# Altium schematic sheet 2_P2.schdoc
size 848 x 601 mm; Symbol: Sheet-Symbol_A0; Device: Sheet-Symbol_A0; Company: 嘉立创EDA; Version: V1.0; Page Size: A0; @Project Name: MX无人机3; @Page Count: 2; @Update Date: 2025-03-07; @Create Date: 2025-02-27; @Schematic Name: Schematic4; @Page No: 2; @Page Name: P2; @Board Name: 遥控; @Create Time: 13:19:18; @Update Time: 19:04:30; Width: 3304; Height: 2338; Region Start: 1; X Region Count: 6; Y Region Count: 4; Blade Width: 10; Title Block Position: 3
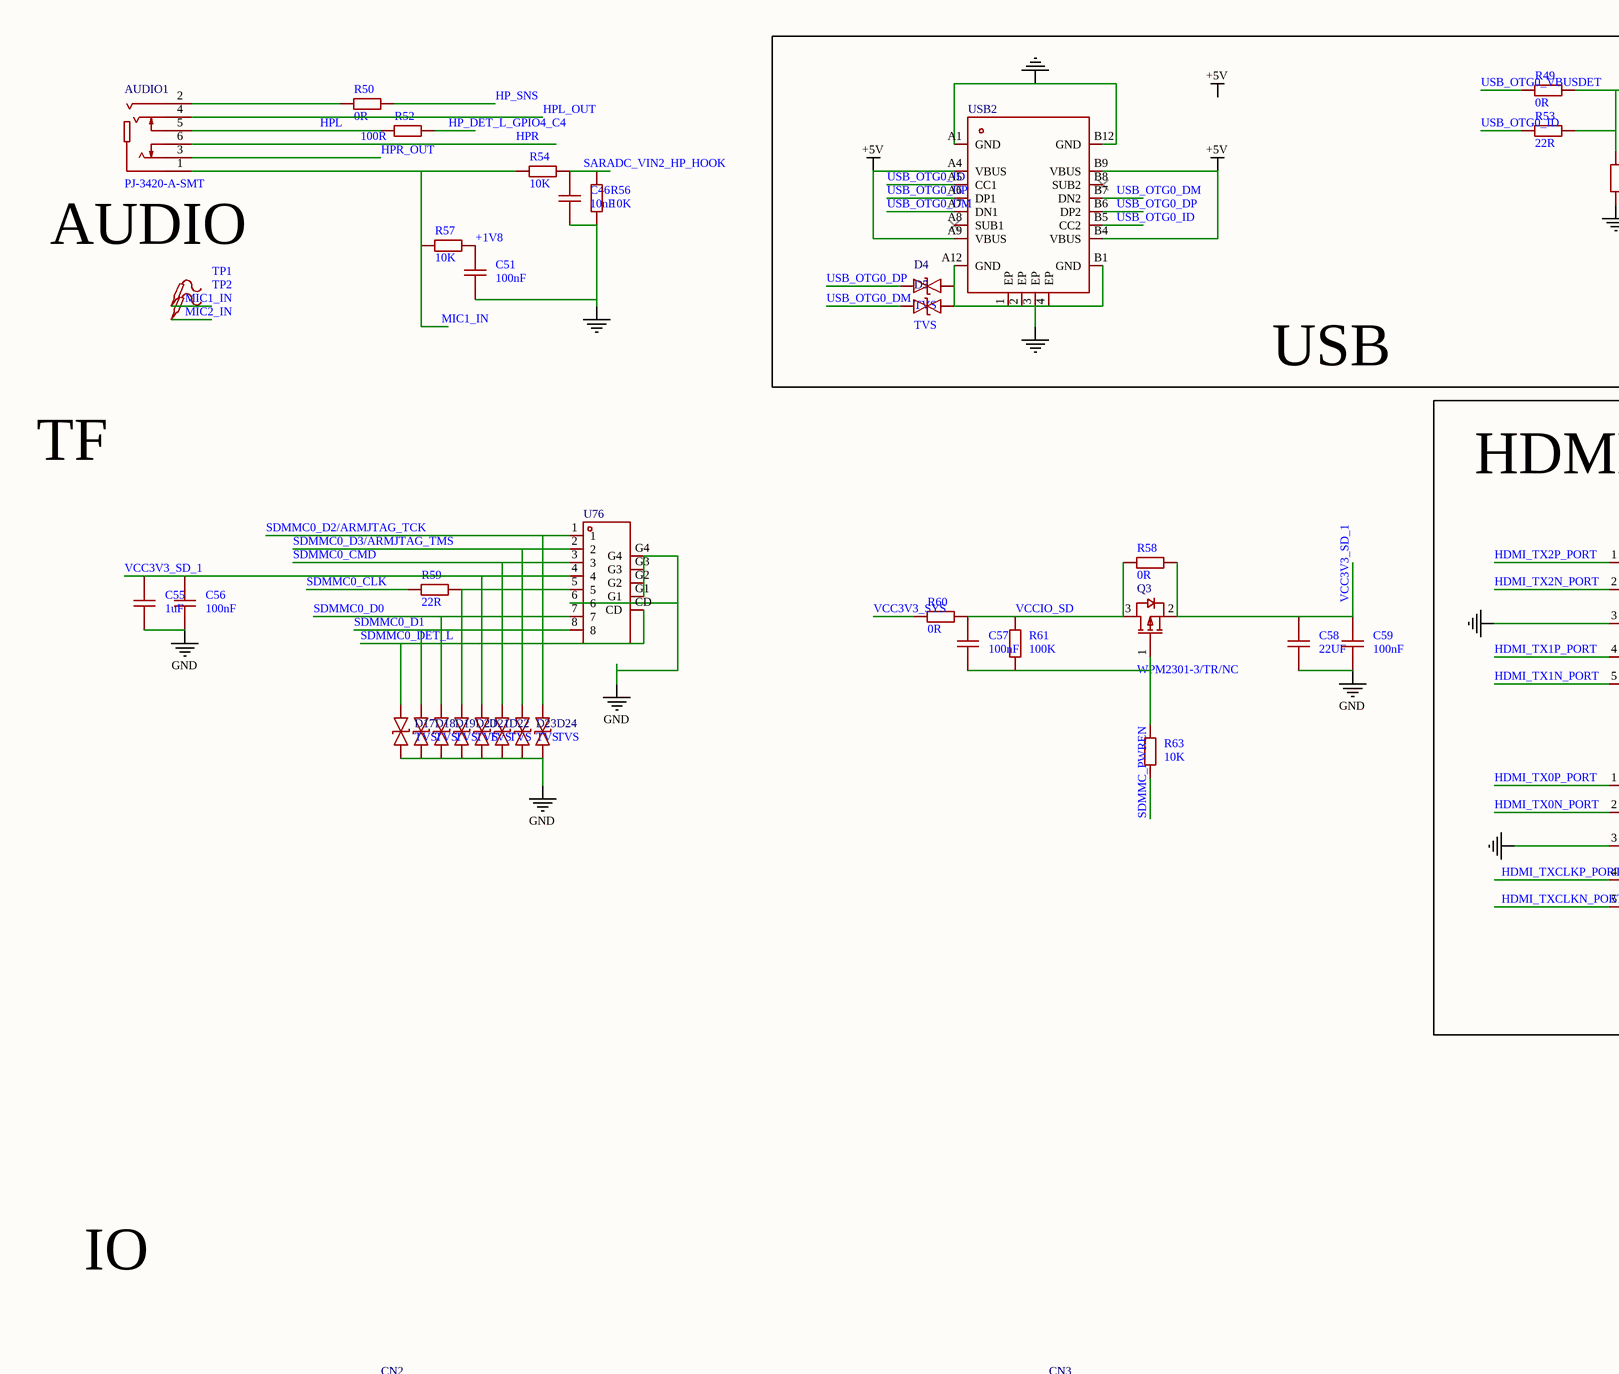
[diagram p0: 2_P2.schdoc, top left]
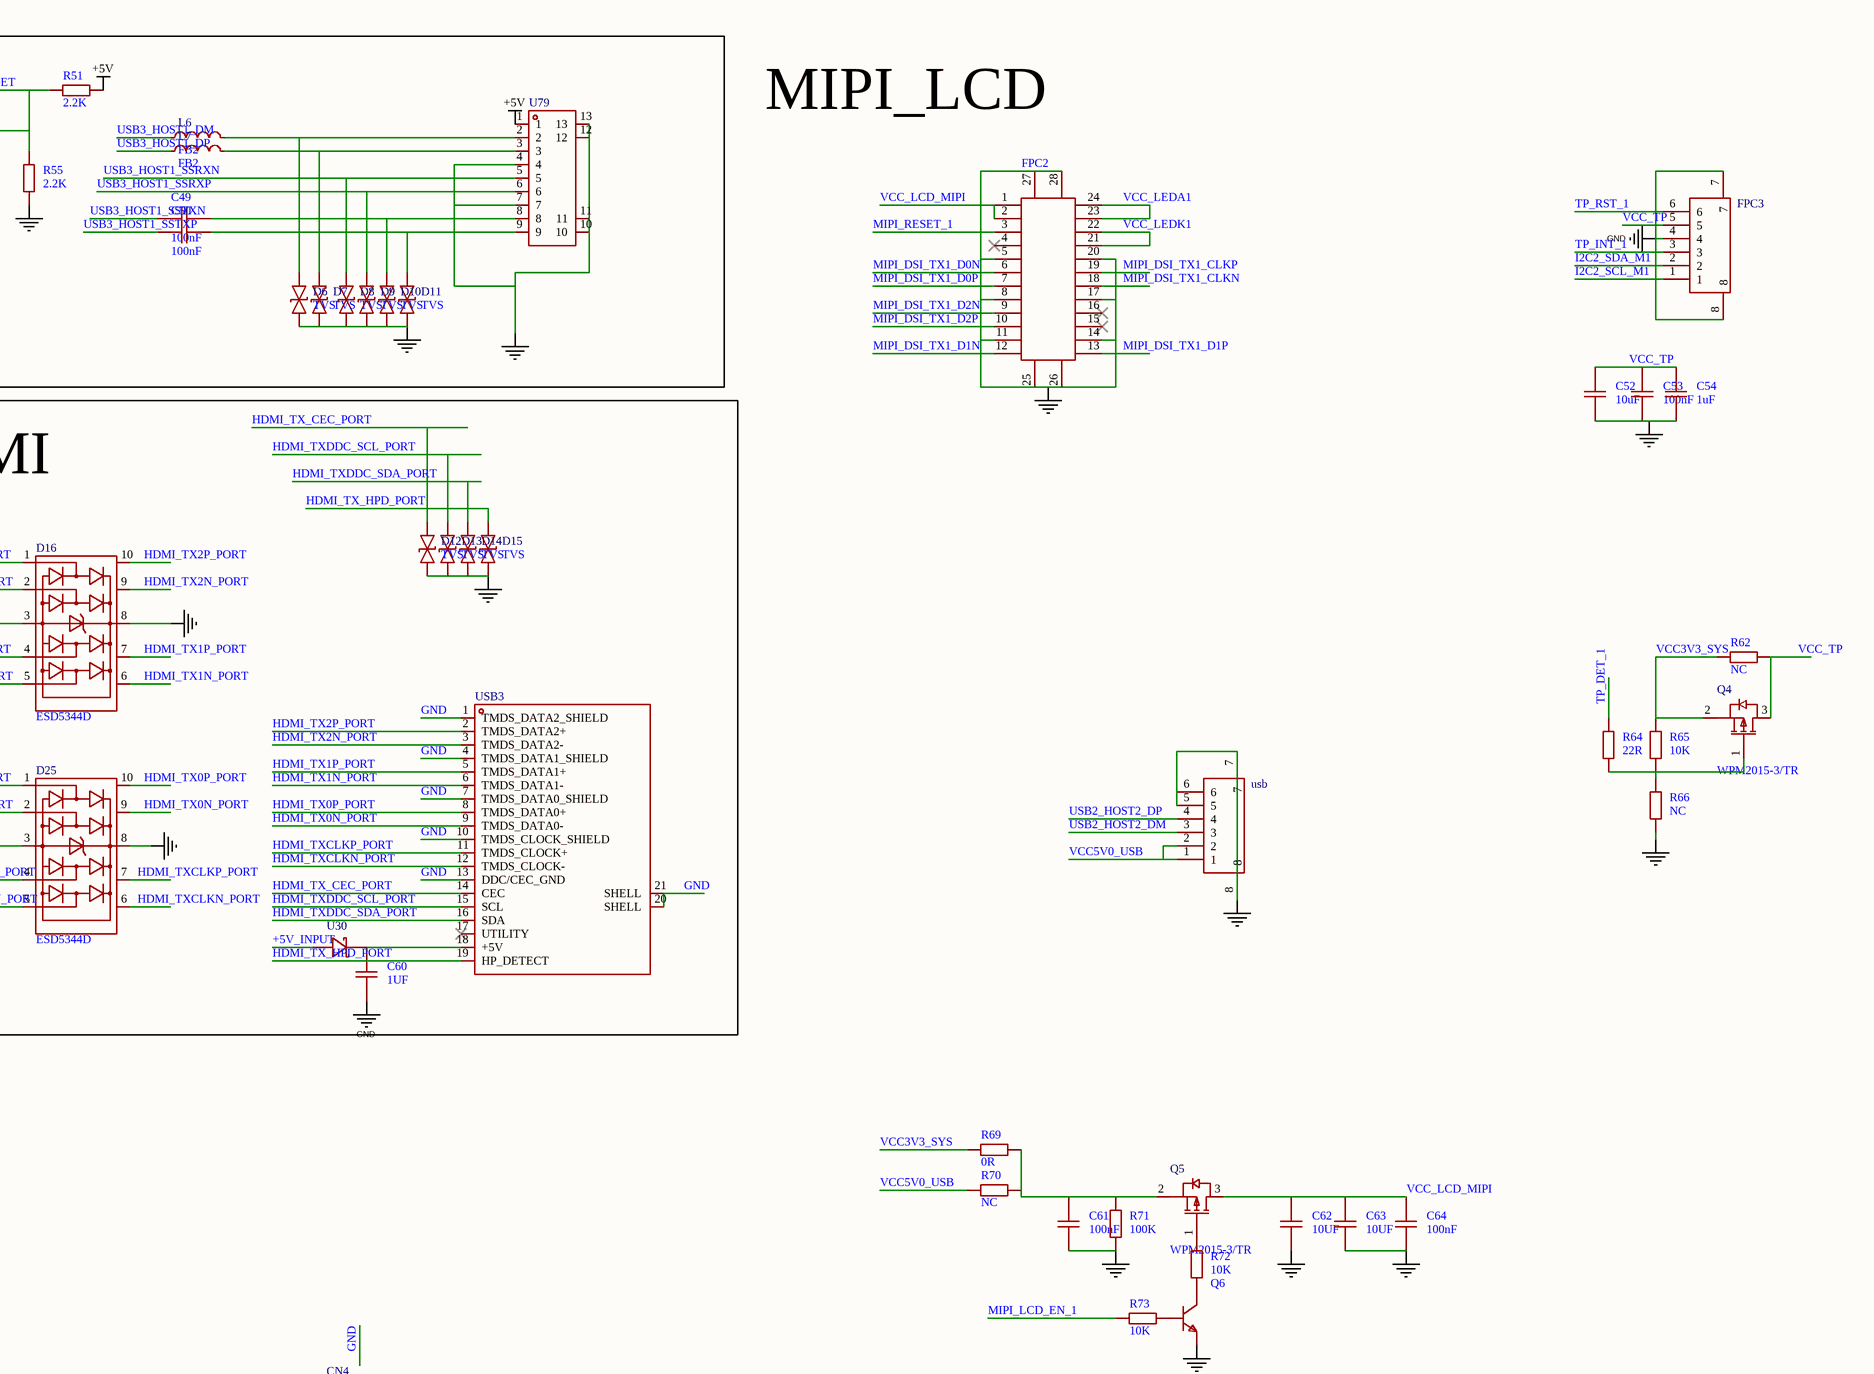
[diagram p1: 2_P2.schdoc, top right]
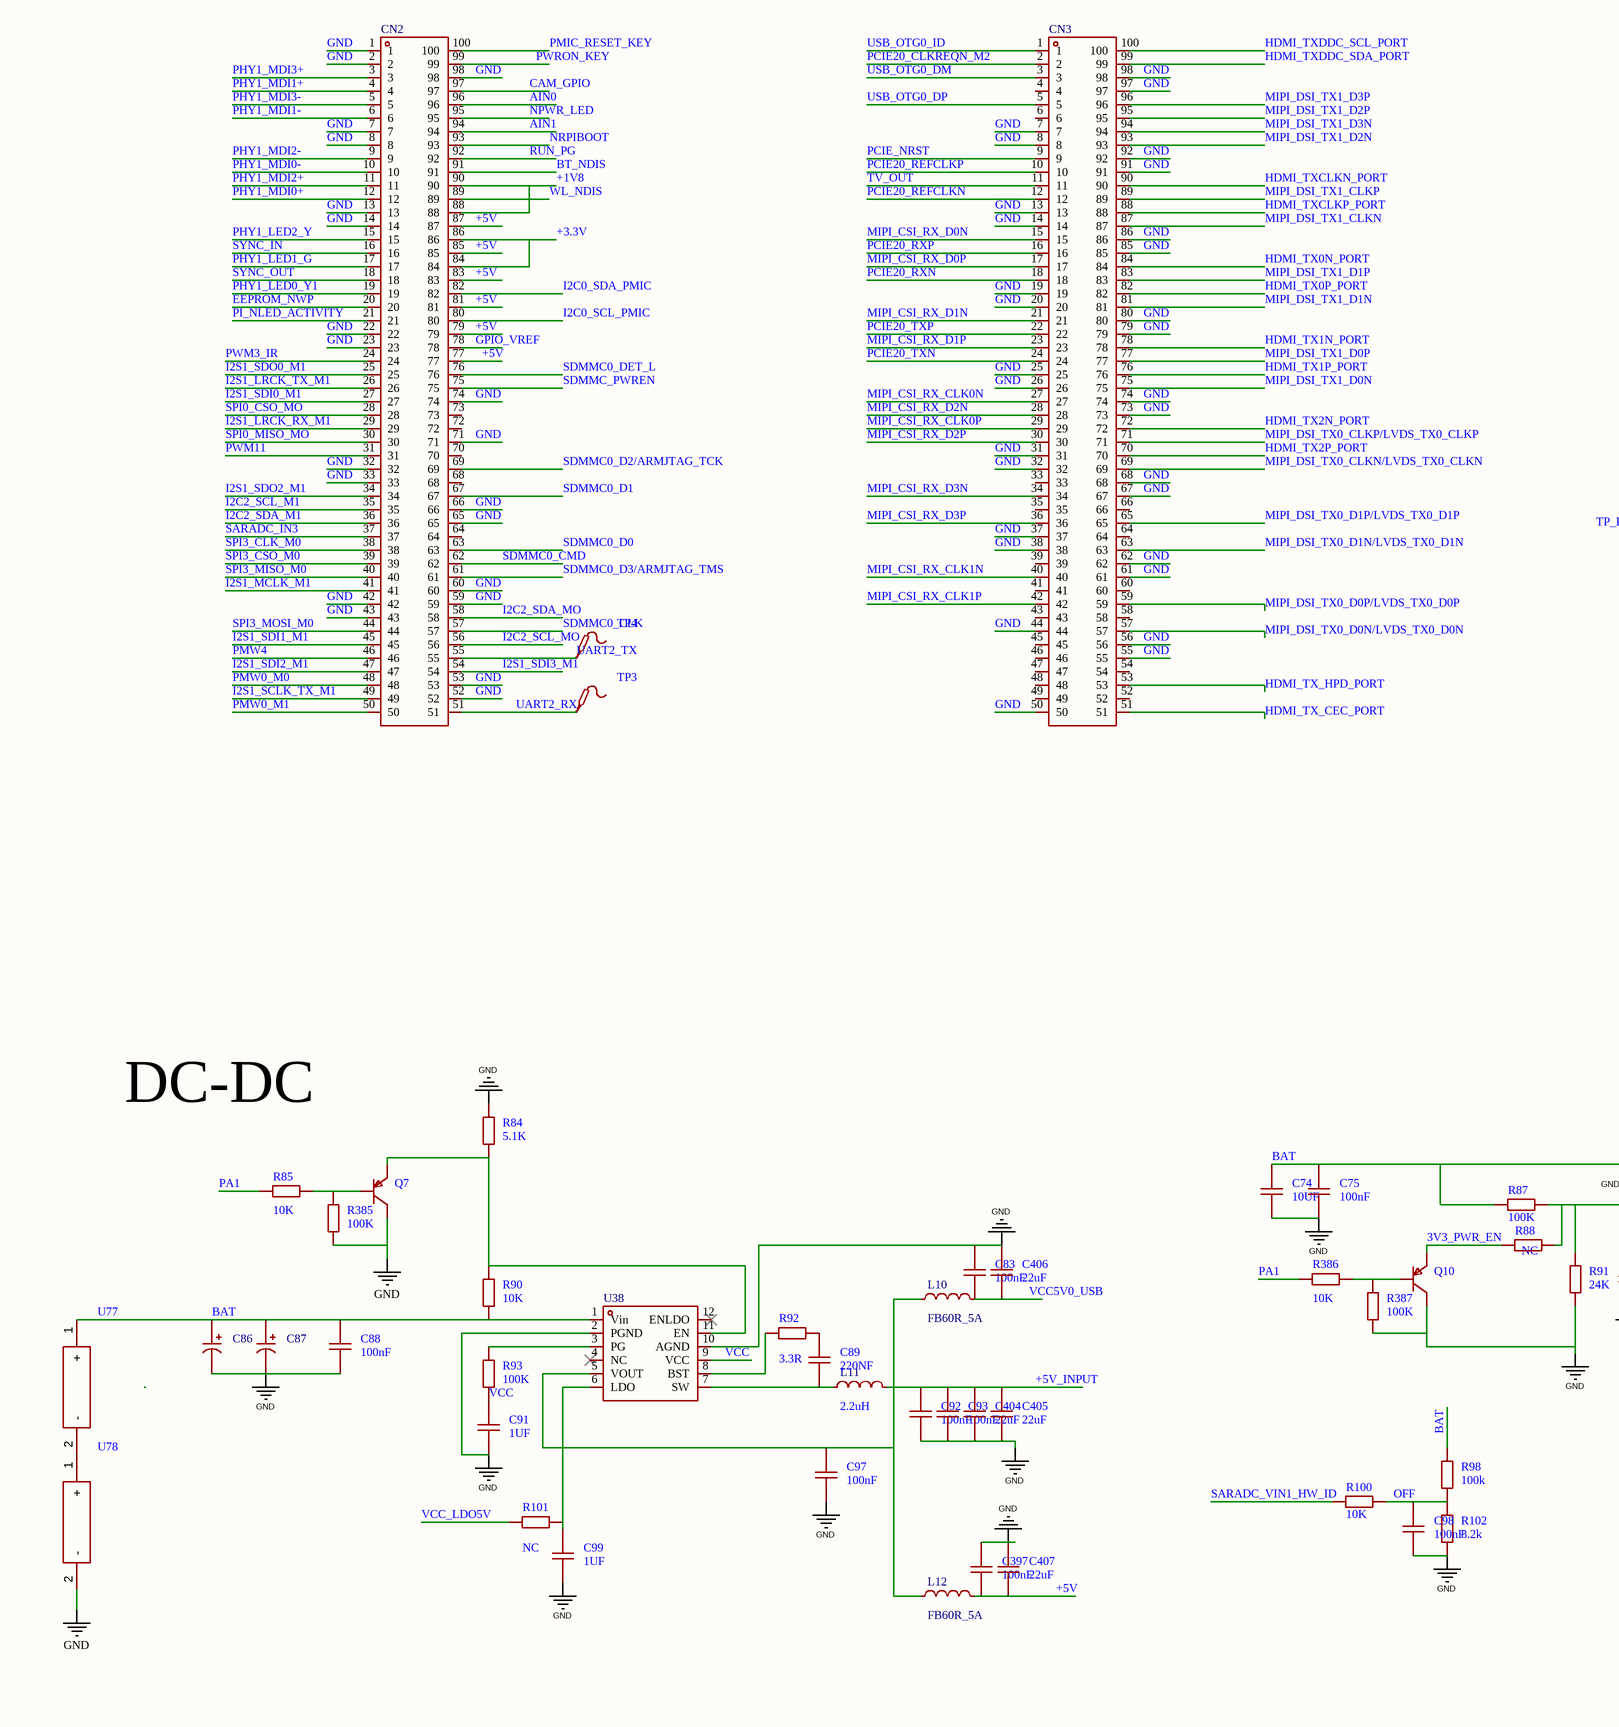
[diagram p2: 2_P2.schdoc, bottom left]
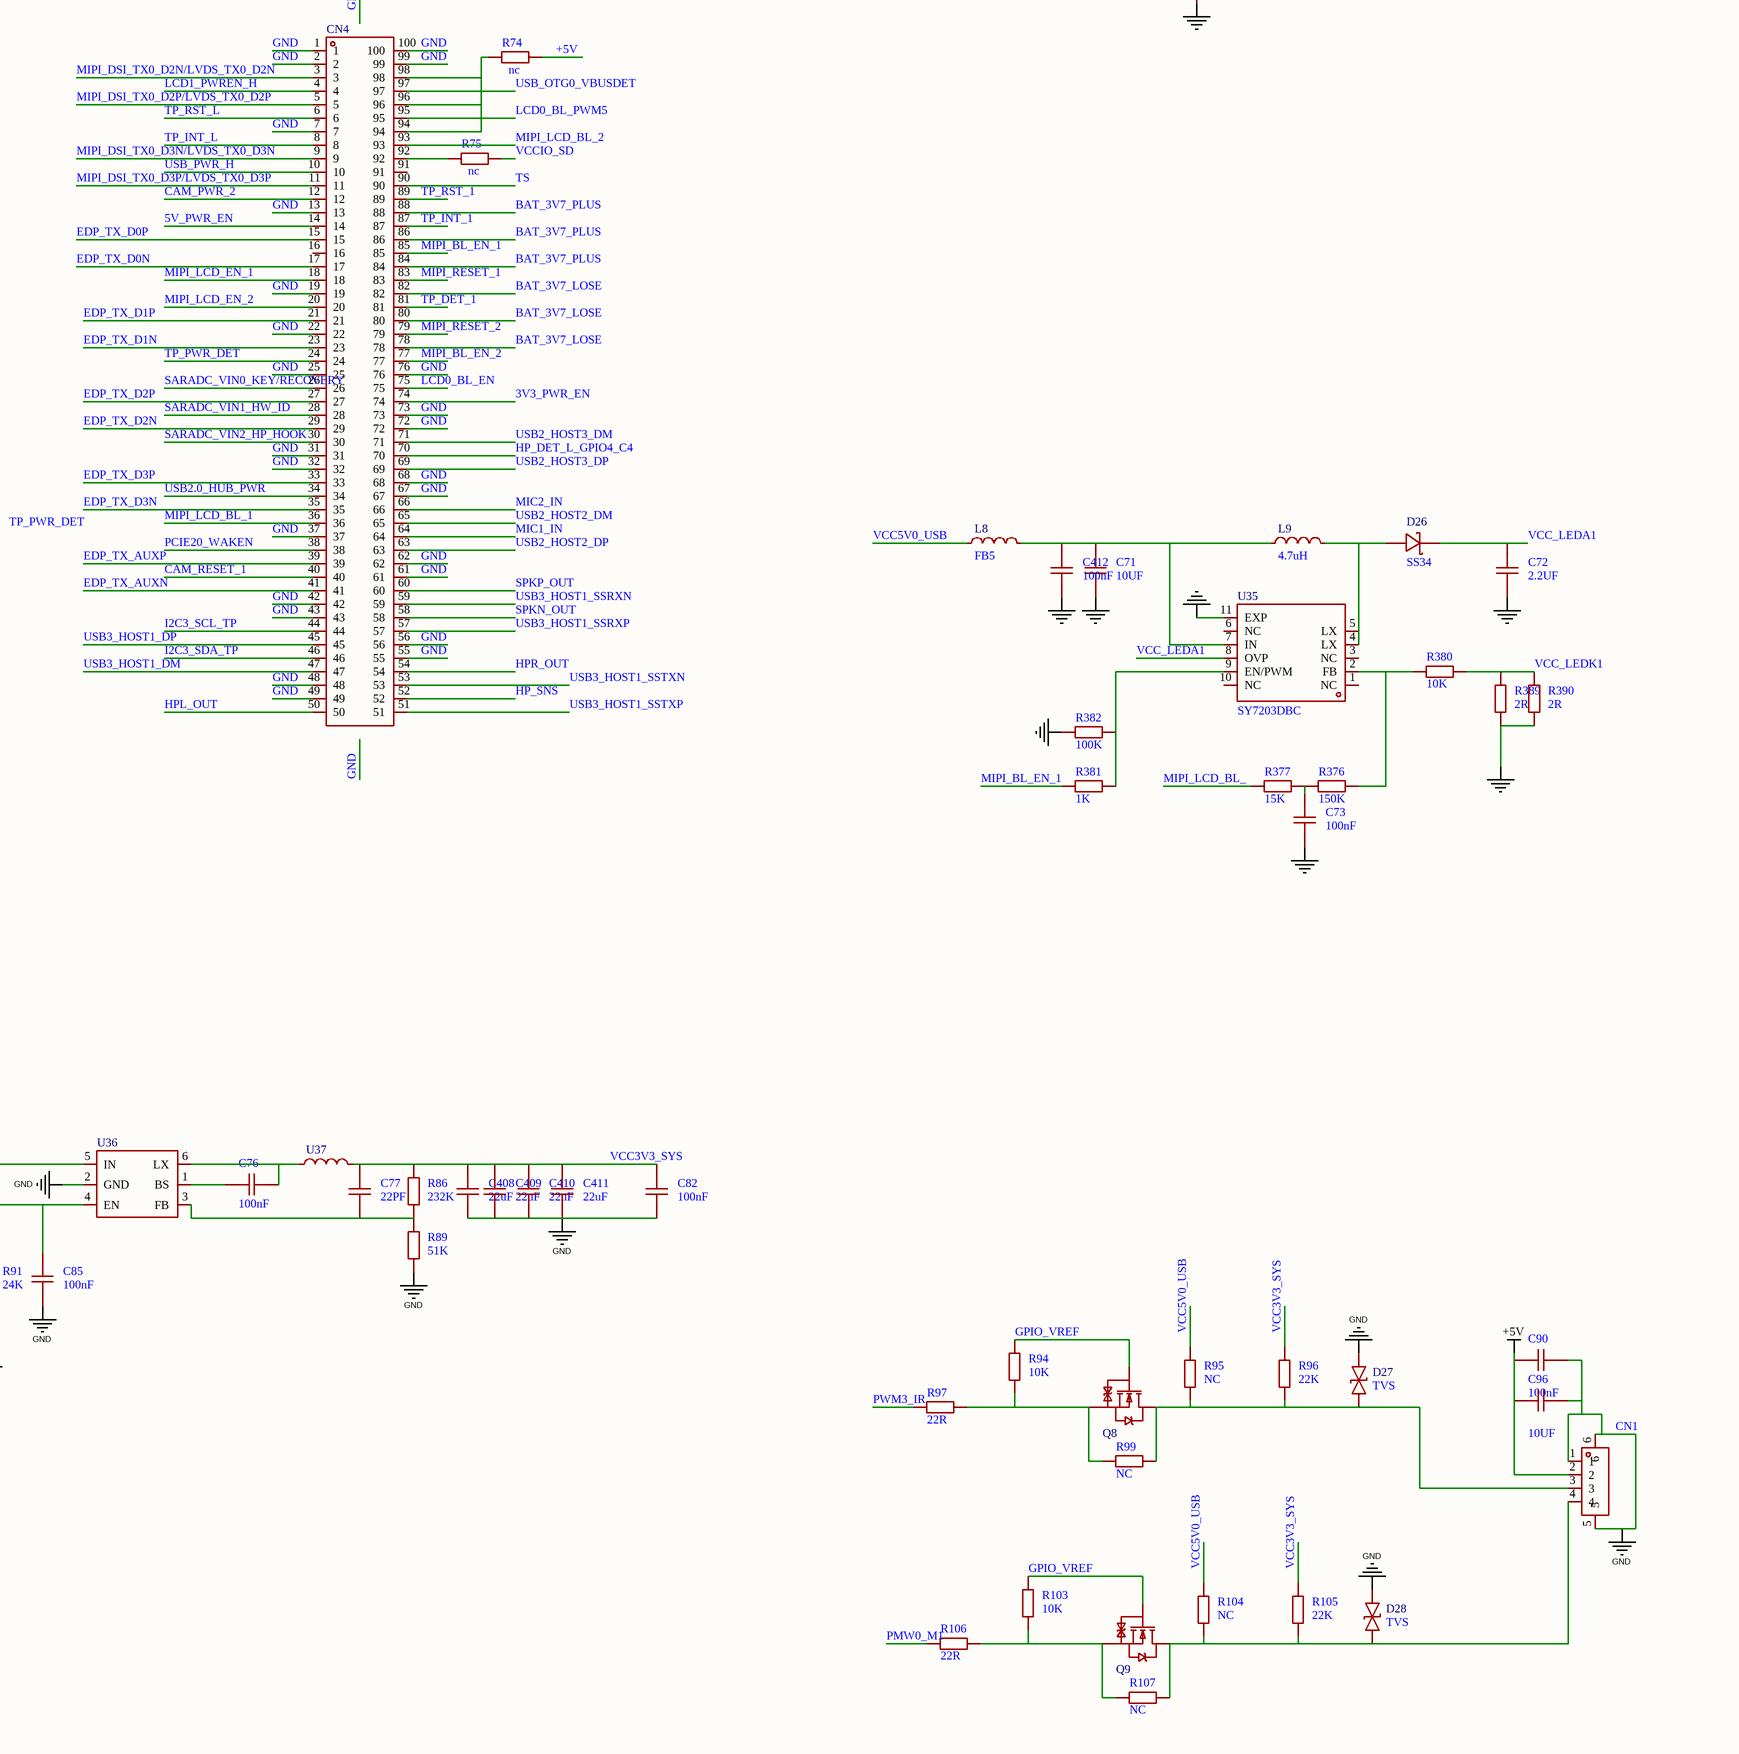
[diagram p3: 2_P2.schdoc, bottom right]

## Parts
AUDIO1  PJ-3420-A-SMT  [AUDIO-SMD_PJ-3420-A-SMT_C319102]
C46  10nF  [C0402]
C49  100nF  [C0402]
C50  100nF  [C0402]
C51  100nF  [C0402]
C52  10uF  [C0603]
C53  100nF  [C0603]
C54  1uF  [C0603]
C55  1uF  [C0603]
C56  100nF  [C0603]
C57  100nF  [C0402]
C58  22UF  [C0603]
C59  100nF  [C0402]
C60  1UF  [C0402]
C61  100nF  [C0603]
C62  10UF  [C0603]
C63  10UF  [C0603]
C64  100nF  [C0603]
C71  10UF  [C0603]
C72  2.2UF  [C0603]
C73  100nF  [C0603]
C74  10UF  [C0603]
C75  100nF  [C0603]
C76  100nF  [C0603]
C77  22PF  [C0603]
C82  100nF  [C0603]
C83  100nF  [C0603]
C85  100nF  [C0603]
C86  CS22UF35V5*5.4  [CAP-SMD_BD5.0-L5.3-W5.3-LS6.0-FD]  (value not drawn)
C87  CS22UF35V5*5.4  [CAP-SMD_BD5.0-L5.3-W5.3-LS6.0-FD]  (value not drawn)
C88  100nF  [C0603]
C89  220NF  [C0603]
C90  100nF  [C0402]
C91  1UF  [C0603]
C92  100nF  [C0603]
C93  100nF  [C0603]
C96  10UF  [C0402]
C97  100nF  [C0603]
C98  100nF  [C0402]
C99  1UF  [C0603]
C397  100nF  [C0603]
C404  22uF  [C0805]
C405  22uF  [C0805]
C406  22uF  [C0805]
C407  22uF  [C0805]
C408  22uF  [C0805]
C409  22uF  [C0805]
C410  22uF  [C0805]
C411  22uF  [C0805]
C412  100nF  [C0402]
CN1  W10001-104MSNER1  [CONN-SMD_4P-P1.00_TXGA_FWF10002-S04S24W5M]  (value not drawn)
CN2  DF40HC(3.0)-100DS-0.4V(58)  [CONN-SMD_DF40HC-3.0-100DS-0.4V-51]  (value not drawn)
CN3  DF40HC(3.0)-100DS-0.4V(58)  [CONN-SMD_DF40HC-3.0-100DS-0.4V-51]  (value not drawn)
CN4  DF40HC(3.0)-100DS-0.4V(58)  [CONN-SMD_DF40HC-3.0-100DS-0.4V-51]  (value not drawn)
D4  TVS  [SOD-523_L1.2-W0.8-LS1.6-BI]
D5  TVS  [SOD-523_L1.2-W0.8-LS1.6-BI]
D6  TVS  [SOD-523_L1.2-W0.8-LS1.6-BI]
D7  TVS  [SOD-523_L1.2-W0.8-LS1.6-BI]
D8  TVS  [SOD-523_L1.2-W0.8-LS1.6-BI]
D9  TVS  [SOD-523_L1.2-W0.8-LS1.6-BI]
D10  TVS  [SOD-523_L1.2-W0.8-LS1.6-BI]
D11  TVS  [SOD-523_L1.2-W0.8-LS1.6-BI]
D12  TVS  [SOD-523_L1.2-W0.8-LS1.6-BI]
D13  TVS  [SOD-523_L1.2-W0.8-LS1.6-BI]
D14  TVS  [SOD-523_L1.2-W0.8-LS1.6-BI]
D15  TVS  [SOD-523_L1.2-W0.8-LS1.6-BI]
D16  ESD5344D  [DFN2510-10_L2.5-W1.0-P0.50-BL]
D17  TVS  [SOD-523_L1.2-W0.8-LS1.6-BI]
D18  TVS  [SOD-523_L1.2-W0.8-LS1.6-BI]
D19  TVS  [SOD-523_L1.2-W0.8-LS1.6-BI]
D20  TVS  [SOD-523_L1.2-W0.8-LS1.6-BI]
D21  TVS  [SOD-523_L1.2-W0.8-LS1.6-BI]
D22  TVS  [SOD-523_L1.2-W0.8-LS1.6-BI]
D23  TVS  [SOD-523_L1.2-W0.8-LS1.6-BI]
D24  TVS  [SOD-523_L1.2-W0.8-LS1.6-BI]
D25  ESD5344D  [DFN2510-10_L2.5-W1.0-P0.50-BL]
D26  SS34  [SMA_L4.3-W2.6-LS5.2-RD]
D27  TVS  [SOD-523_L1.2-W0.8-LS1.6-BI]
D28  TVS  [SOD-523_L1.2-W0.8-LS1.6-BI]
FPC2  (no value)  [OK-06F024-04]
FPC3  AFC01-S06FCA-00  [FPC-SMD_P0.50-6P_AFC01-S06FCA-00]  (value not drawn)
L6  FB2  [L0402]
L7  FB2  [L0402]
L8  FB5  [L0603]
L9  4.7uH  [IND-SMD_L4.0-W4.0_LQH44PN2R2MP0L]
L10  FB60R_5A  [L1206]
L11  2.2uH  [IND-SMD_L5.4-W5.1_SPM5020]
L12  FB60R_5A  [L1206]
Q3  WPM2301-3/TR/NC  [SOT-23-3_L2.9-W1.3-P1.90-LS2.4-BR]
Q4  WPM2015-3/TR  [SOT-23-3_L2.9-W1.6-P1.90-LS2.8-BR]
Q5  WPM2015-3/TR  [SOT-23-3_L2.9-W1.6-P1.90-LS2.8-BR]
Q6  (no value)  [S8050_SOT-23]
Q7  (no value)  [S8550P_SOT]
Q8  2SK3018FPDT106  [SOT-323-3_L2.0-W1.3-P1.30-LS2.1-BR]  (value not drawn)
Q9  2SK3018FPDT106  [SOT-323-3_L2.0-W1.3-P1.30-LS2.1-BR]  (value not drawn)
Q10  (no value)  [S8550P_SOT]
R49  0R  [R0402]
R50  0R  [R0402]
R51  2.2K  [R0402]
R52  100R  [R0402]
R53  22R  [R0402]
R54  10K  [R0402]
R55  2.2K  [R0402]
R56  10K  [R0402]
R57  10K  [R0402]
R58  0R  [R0603]
R59  22R  [R0402]
R60  0R  [R0603]
R61  100K  [R0603]
R62  NC  [R0603]
R63  10K  [R0603]
R64  22R  [R0603]
R65  10K  [R0603]
R66  NC  [R0603]
R69  0R  [R0603]
R70  NC  [R0603]
R71  100K  [R0603]
R72  10K  [R0603]
R73  10K  [R0603]
R74  nc  [R0603]
R75  nc  [R0603]
R84  5.1K  [R0603]
R85  10K  [R0603]
R86  232K  [R0603]
R87  100K  [R0603]
R88  NC  [R0603]
R89  51K  [R0603]
R90  10K  [R0603]
R91  24K  [R0603]
R92  3.3R  [R0603]
R93  100K  [R0603]
R94  10K  [R0603]
R95  NC  [R0603]
R96  22K  [R0603]
R97  22R  [R0603]
R98  100k  [R0603]
R99  NC  [R0603]
R100  10K  [R0603]
R101  NC  [R0603]
R102  8.2k  [R0603]
R103  10K  [R0603]
R104  NC  [R0603]
R105  22K  [R0603]
R106  22R  [R0603]
R107  NC  [R0603]
R376  150K  [R0402]
R377  15K  [R0402]
R380  10K  [R0402]
R381  1K  [R0402]
R382  100K  [R0402]
R385  100K  [R0603]
R386  10K  [R0603]
R387  100K  [R0603]
R389  2R  [R0805]
R390  2R  [R0805]
TP1  (no value)  [Test-Point-0.5mm]
TP2  (no value)  [Test-Point-0.5mm]
TP3  (no value)  [Test-Point-0.5mm]
TP4  (no value)  [Test-Point-0.5mm]
U30  B5819WS  [SOD-123_L2.8-W1.8-LS3.7-FD]  (value not drawn)
U35  SY7203DBC  [DFN-10_L3.0-W3.0-P0.50-BL-EP]
U36  SY8113BADC  [TSOT-23-6_L2.9-W1.6-P0.95-LS2.8-BR]  (value not drawn)
U37  4.7uH 3A  [IND-SMD_L7.3-W7.3_GSDRH74P]  (value not drawn)
U38  NB679GD-Z  [QFN-12_L3.0-W2.0-P0.5-TL_NB680]  (value not drawn)
U76  micro sd卡座  [MICRO-USB-SMD_MICRO-SD]  (value not drawn)
U77  21700  [21700]  (value not drawn)
U78  21700  [21700]  (value not drawn)
U79  Type-A_USB3.0_3.4mm  [USB-A-SMD_TYPE-A_USB3.0_3.4MM]  (value not drawn)
usb  AFC01-S06FCA-00  [FPC-SMD_P0.50-6P_AFC01-S06FCA-00]  (value not drawn)
USB2  KH-TYPE-C-16P  [USB-C-SMD_KH-TYPE-C-16P]  (value not drawn)
USB3  KH-HDMI-0002  [HDMI-SMD_KH-HDMI-0002]  (value not drawn)

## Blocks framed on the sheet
USB: C49 C50 D4-D11 L6 L7 R49 R51 R53 R55 U79 USB2
HDMI: C60 D12-D16 D25 U30 USB3

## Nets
+5V: C90.1 C96.1 C397.2 C407.1 CN1.2 CN2.77 CN2.79 CN2.81 CN2.83 CN2.85 CN2.87 L12.2 R51.2 R74.2 U79.1 USB2.A4(VBUS) USB2.A9(VBUS) USB2.B4(VBUS) USB2.B9(VBUS)
GND: C46.1 C51.1 C52.1 C53.1 C54.1 C55.1 C56.1 C58.1 C59.1 C60.1 C61.2 C62.1 C63.1 C64.1 C71.1 C72.1 C73.1 C74.1 C75.1 C82.1 C83.1 C85.1 C86.2 C87.2 C88.1 C90.2 C91.1 C92.1 C93.1 C96.2 C97.2 C98.1 C99.1 C397.1 C404.1 C405.1 C406.2 C407.2 C408.1 C409.1 C410.1 C411.1 C412.1 CN1.1 CN1.5 CN1.6 CN2.1 CN2.2 CN2.7 CN2.8 CN2.13 CN2.14 CN2.22 CN2.23 CN2.32 CN2.33 CN2.42 CN2.43 CN2.52 CN2.53 CN2.59 CN2.60 CN2.65 CN2.66 CN2.71 CN2.74 CN2.98 CN3.7 CN3.8 CN3.13 CN3.14 CN3.19 CN3.20 CN3.25 CN3.26 CN3.31 CN3.32 CN3.37 CN3.38 CN3.44 CN3.50 CN3.55 CN3.56 CN3.61 CN3.62 CN3.67 CN3.68 CN3.73 CN3.74 CN3.79 CN3.80 CN3.85 CN3.86 CN3.91 CN3.92 CN3.97 CN3.98 CN4.1 CN4.2 CN4.7 CN4.13 CN4.19 CN4.22 CN4.25 CN4.31 CN4.32 CN4.37 CN4.42 CN4.43 CN4.48 CN4.49 CN4.55 CN4.56 CN4.61 CN4.62 CN4.67 CN4.68 CN4.72 CN4.73 CN4.76 CN4.99 CN4.100 D4.1 D5.1 D6.1 D7.1 D8.1 D9.1 D10.1 D11.1 D12.1 D13.1 D14.1 D15.1 D16.3 D16.8 D17.1 D18.1 D19.1 D20.1 D21.1 D22.1 D23.1 D24.1 D25.3 D25.8 D27.2 D28.2 FPC2.5 FPC2.8 FPC2.11 FPC2.14 FPC2.17 FPC2.20 FPC2.25 FPC2.26 FPC2.27 FPC2.28 FPC3.4 FPC3.7 FPC3.8 Q6.2 Q7.3(C) Q10.3(C) R55.1 R56.1 R66.1 R71.2 R84.1 R89.1 R91.1 R102.1 R382.2 R385.1 R387.1 R389.1 R390.1 U35.11(EXP) U36.2(GND) U38.2(PGND) U38.10(AGND) U76.6 U76.G1 U76.G2 U76.G3 U76.G4 U78.2(-) U79.4 U79.7 U79.10 U79.11 U79.12 U79.13 usb.5 usb.6 usb.7 usb.8 USB2.1(EP) USB2.2(EP) USB2.3(EP) USB2.4(EP) USB2.A1(GND) USB2.A12(GND) USB2.B1(GND) USB2.B12(GND) USB3.1(TMDS_DATA2_SHIELD) USB3.4(TMDS_DATA1_SHIELD) USB3.7(TMDS_DATA0_SHIELD) USB3.10(TMDS_CLOCK_SHIELD) USB3.13(DDC/CEC_GND) USB3.20(SHELL) USB3.21(SHELL)
3V3_PWR_EN: CN4.74 Q10.2(E) R88.2
5V_PWR_EN: CN4.14
+1V8: C51.2 CN2.88 CN2.90 R57.2
+3.3V: CN2.84 CN2.86
+5V_INPUT: C92.2 C93.2 C97.1 C404.2 C405.2 L10.1 L11.2 L12.1 U30.1(A) U38.5(VOUT)
AIN0: CN2.96
AIN1: CN2.94
BAT: C74.2 C75.2 C86.1 C87.1 C88.2 R87.2 R90.2 R98.2 U36.5(IN) U38.1(Vin) U77.1(+)
BAT_3V7_LOSE: CN4.78 CN4.80 CN4.82
BAT_3V7_PLUS: CN4.84 CN4.86 CN4.88
BT_NDIS: CN2.91
CAM_GPIO: CN2.97
CAM_PWR_2: CN4.12
CAM_RESET_1: CN4.40
EDP_TX_AUXN: CN4.41
EDP_TX_AUXP: CN4.39
EDP_TX_D0N: CN4.17
EDP_TX_D0P: CN4.15
EDP_TX_D1N: CN4.23
EDP_TX_D1P: CN4.21
EDP_TX_D2N: CN4.29
EDP_TX_D2P: CN4.27
EDP_TX_D3N: CN4.35
EDP_TX_D3P: CN4.33
EEPROM_NWP: CN2.20
GPIO_VREF: CN2.78 Q8.1(G) Q9.1(G) R94.2 R103.2
HDMI_TX0N_PORT: CN3.84 D25.2 D25.9 USB3.9(TMDS_DATA0-)
HDMI_TX0P_PORT: CN3.82 D25.1 D25.10 USB3.8(TMDS_DATA0+)
HDMI_TX1N_PORT: CN3.78 D16.5 D16.6 USB3.6(TMDS_DATA1-)
HDMI_TX1P_PORT: CN3.76 D16.4 D16.7 USB3.5(TMDS_DATA1+)
HDMI_TX2N_PORT: CN3.72 D16.2 D16.9 USB3.3(TMDS_DATA2-)
HDMI_TX2P_PORT: CN3.70 D16.1 D16.10 USB3.2(TMDS_DATA2+)
HDMI_TX_CEC_PORT: CN3.51 D12.2 USB3.14(CEC)
HDMI_TX_HPD_PORT: CN3.53 D15.2 USB3.19(HP_DETECT)
HDMI_TXCLKN_PORT: CN3.90 D25.5 D25.6 USB3.12(TMDS_CLOCK-)
HDMI_TXCLKP_PORT: CN3.88 D25.4 D25.7 USB3.11(TMDS_CLOCK+)
HDMI_TXDDC_SCL_PORT: CN3.100 D13.2 USB3.15(SCL)
HDMI_TXDDC_SDA_PORT: CN3.99 D14.2 USB3.16(SDA)
HP_DET_L_GPIO4_C4: CN4.70 R52.2
HP_SNS: CN4.52 R50.2
HPL: AUDIO1.5 R52.1
HPL_OUT: AUDIO1.4 CN4.50
HPR: AUDIO1.6
HPR_OUT: AUDIO1.3 CN4.54
I2C0_SCL_PMIC: CN2.80
I2C0_SDA_PMIC: CN2.82
I2C2_SCL_M1: CN2.35 FPC3.1
I2C2_SCL_MO: CN2.56
I2C2_SDA_M1: CN2.36 FPC3.2
I2C2_SDA_MO: CN2.58
I2C3_SCL_TP: CN4.44
I2C3_SDA_TP: CN4.46
I2S1_LRCK_RX_M1: CN2.29
I2S1_LRCK_TX_M1: CN2.26
I2S1_MCLK_M1: CN2.41
I2S1_SCLK_TX_M1: CN2.49
I2S1_SDI0_M1: CN2.27
I2S1_SDI1_M1: CN2.45
I2S1_SDI2_M1: CN2.47
I2S1_SDI3_M1: CN2.54
I2S1_SDO0_M1: CN2.25
I2S1_SDO2_M1: CN2.34
LCD0_BL_EN: CN4.75
LCD0_BL_PWM5: CN4.95
LCD1_PWREN_H: CN4.4
MIC1_IN: AUDIO1.1 CN4.64 R54.1 R57.1 TP1.1
MIC2_IN: CN4.66 TP2.1
MIPI_BL_EN_1: CN4.85 R381.2
MIPI_BL_EN_2: CN4.77
MIPI_CSI_RX_CLK0N: CN3.27
MIPI_CSI_RX_CLK0P: CN3.29
MIPI_CSI_RX_CLK1N: CN3.40
MIPI_CSI_RX_CLK1P: CN3.42
MIPI_CSI_RX_D0N: CN3.15
MIPI_CSI_RX_D0P: CN3.17
MIPI_CSI_RX_D1N: CN3.21
MIPI_CSI_RX_D1P: CN3.23
MIPI_CSI_RX_D2N: CN3.28
MIPI_CSI_RX_D2P: CN3.30
MIPI_CSI_RX_D3N: CN3.34
MIPI_CSI_RX_D3P: CN3.36
MIPI_DSI_TX0_CLKN/LVDS_TX0_CLKN: CN3.69
MIPI_DSI_TX0_CLKP/LVDS_TX0_CLKP: CN3.71
MIPI_DSI_TX0_D0N/LVDS_TX0_D0N: CN3.57
MIPI_DSI_TX0_D0P/LVDS_TX0_D0P: CN3.59
MIPI_DSI_TX0_D1N/LVDS_TX0_D1N: CN3.63
MIPI_DSI_TX0_D1P/LVDS_TX0_D1P: CN3.65
MIPI_DSI_TX0_D2N/LVDS_TX0_D2N: CN4.3
MIPI_DSI_TX0_D2P/LVDS_TX0_D2P: CN4.5
MIPI_DSI_TX0_D3N/LVDS_TX0_D3N: CN4.9
MIPI_DSI_TX0_D3P/LVDS_TX0_D3P: CN4.11
MIPI_DSI_TX1_CLKN: CN3.87 FPC2.18
MIPI_DSI_TX1_CLKP: CN3.89 FPC2.19
MIPI_DSI_TX1_D0N: CN3.75 FPC2.6
MIPI_DSI_TX1_D0P: CN3.77 FPC2.7
MIPI_DSI_TX1_D1N: CN3.81 FPC2.12
MIPI_DSI_TX1_D1P: CN3.83 FPC2.13
MIPI_DSI_TX1_D2N: CN3.93 FPC2.9
MIPI_DSI_TX1_D2P: CN3.95 FPC2.10
MIPI_DSI_TX1_D3N: CN3.94
MIPI_DSI_TX1_D3P: CN3.96
MIPI_LCD_BL_: R377.1
MIPI_LCD_BL_1: CN4.36
MIPI_LCD_BL_2: CN4.93
MIPI_LCD_EN_1: CN4.18 R73.1
MIPI_LCD_EN_2: CN4.20
MIPI_RESET_1: CN4.83 FPC2.3
MIPI_RESET_2: CN4.79
NPWR_LED: CN2.95
NRPIBOOT: CN2.93
OFF: C98.2 R98.1 R100.1 R102.2
PA1: R85.1 R386.1
PCIE20_CLKREQN_M2: CN3.2
PCIE20_REFCLKN: CN3.12
PCIE20_REFCLKP: CN3.10
PCIE20_RXN: CN3.18
PCIE20_RXP: CN3.16
PCIE20_TXN: CN3.24
PCIE20_TXP: CN3.22
PCIE20_WAKEN: CN4.38
PCIE_NRST: CN3.9
PHY1_LED0_Y1: CN2.19
PHY1_LED1_G: CN2.17
PHY1_LED2_Y: CN2.15
PHY1_MDI0+: CN2.12
PHY1_MDI0-: CN2.10
PHY1_MDI1+: CN2.4
PHY1_MDI1-: CN2.6
PHY1_MDI2+: CN2.11
PHY1_MDI2-: CN2.9
PHY1_MDI3+: CN2.3
PHY1_MDI3-: CN2.5
PI_NLED_ACTIVITY: CN2.21
PMIC_RESET_KEY: CN2.100
PMW0_M0: CN2.48
PMW0_M1: CN2.50 R106.2
PMW4: CN2.46
PWM3_IR: CN2.24 R97.2
PWM11: CN2.31
PWRON_KEY: CN2.99
RUN_PG: CN2.92
SARADC_IN3: CN2.37
SARADC_VIN0_KEY/RECOVERY: CN4.26
SARADC_VIN1_HW_ID: CN4.28 R100.2
SARADC_VIN2_HP_HOOK: C46.2 CN4.30 R54.2 R56.2
SDMMC0_CLK: CN2.57 R59.1
SDMMC0_CMD: CN2.62 D22.2 U76.3
SDMMC0_D0: CN2.63 D19.2 U76.7
SDMMC0_D1: CN2.67 D18.2 U76.8
SDMMC0_D2/ARMJTAG_TCK: CN2.69 D24.2 U76.1
SDMMC0_D3/ARMJTAG_TMS: CN2.61 D23.2 U76.2
SDMMC0_DET_L: CN2.76 D17.2 U76.CD
SDMMC_PWREN: CN2.75 R63.1
SPI0_CSO_MO: CN2.28
SPI0_MISO_MO: CN2.30
SPI3_CLK_M0: CN2.38
SPI3_CSO_M0: CN2.39
SPI3_MISO_M0: CN2.40
SPI3_MOSI_M0: CN2.44
SPKN_OUT: CN4.58
SPKP_OUT: CN4.60
SYNC_IN: CN2.16
SYNC_OUT: CN2.18
TP_DET_1: CN4.81 R64.2
TP_INT_1: CN4.87 FPC3.3
TP_INT_L: CN4.8
TP_PWR_DET: CN4.24
TP_RST_1: CN4.89 FPC3.6
TP_RST_L: CN4.6
TS: CN4.90
TV_OUT: CN3.11
UART2_RX: CN2.51 TP3.1
UART2_TX: CN2.55 TP4.1
USB2.0_HUB_PWR: CN4.34
USB2_HOST2_DM: CN4.65 usb.3
USB2_HOST2_DP: CN4.63 usb.4
USB2_HOST3_DM: CN4.71
USB2_HOST3_DP: CN4.69
USB3_HOST1_DM: CN4.47 L6.1
USB3_HOST1_DP: CN4.45 L7.1
USB3_HOST1_SSRXN: CN4.59 D8.2 U79.5
USB3_HOST1_SSRXP: CN4.57 D9.2 U79.6
USB3_HOST1_SSTXN: C49.1 CN4.53
USB3_HOST1_SSTXP: C50.1 CN4.51
USB_OTG0_DM: CN3.3 D5.2 USB2.A7(DN1) USB2.B7(DN2)
USB_OTG0_DP: CN3.5 D4.2 USB2.A6(DP1) USB2.B6(DP2)
USB_OTG0_ID: CN3.1 R53.1 USB2.A5(CC1) USB2.B5(CC2)
USB_OTG0_VBUSDET: CN4.97 R49.1
USB_PWR_H: CN4.10
VCC: C91.2 R93.1 U38.9(VCC)
VCC3V3_SD_1: C55.2 C56.2 C58.2 C59.2 D21.2 Q3.2(S) R58.1 U76.4
VCC3V3_SYS: C77.1 C82.2 C408.2 C409.2 C410.2 C411.2 Q4.2(S) R60.1 R62.2 R65.2 R69.1 R86.2 R96.1 R105.1 U37.2
VCC5V0_USB: C83.2 C406.1 L8.1 L10.2 R70.2 R95.1 R104.1 usb.1 usb.2
VCC_LCD_MIPI: C62.2 C63.2 C64.2 FPC2.1 FPC2.2 Q5.3(D)
VCC_LDO5V: R101.1
VCC_LEDA1: C72.2 D26.1(K) FPC2.23 FPC2.24 U35.8(OVP)
VCC_LEDK1: FPC2.21 FPC2.22 R380.1 R389.2 R390.2
VCC_TP: C52.2 C53.2 C54.2 FPC3.5 Q4.3(D) R62.1
VCCIO_SD: C57.2 Q3.3(D) R58.2 R60.2 R61.2 R75.2
WL_NDIS: CN2.89
NetAUDIO1_2: AUDIO1.2 R50.1
NetC49_2: C49.2 D10.2 U79.8
NetC50_2: C50.2 D11.2 U79.9
NetC57_1: C57.1 Q3.1(G) R61.1 R63.2
NetC60_2: C60.2 U30.2(K) USB3.18(+5V)
NetC61_1: C61.1 Q5.2(S) R69.2 R70.1 R71.1
NetC71_2: C71.2 C412.2 L8.2 L9.1 U35.7(IN)
NetC73_2: C73.2 R376.1 R377.2
NetC76_1: C76.1 U36.6(LX) U37.1
NetC76_2: C76.2 U36.1(BS)
NetC77_2: C77.2 R86.1 R89.2 U36.3(FB)
NetC85_2: C85.2 R87.1 R88.1 R91.2 U36.4(EN)
NetC89_1: C89.1 L11.1 U38.7(SW)
NetC89_2: C89.2 R92.2
NetC99_2: C99.2 R101.2 U38.6(LDO)
NetCN1_3: CN1.3 D27.1 Q8.3(D) R95.2 R96.2 R99.1
NetCN1_4: CN1.4 D28.1 Q9.3(D) R104.2 R105.2 R107.1
NetCN4_92: CN4.92 R75.1
NetCN4_94: CN4.94 CN4.96 CN4.98 R74.1
NetD6_2: D6.2 L6.2 U79.2
NetD7_2: D7.2 L7.2 U79.3
NetD20_2: D20.2 R59.2 U76.5
NetD26_2: D26.2(A) L9.2 U35.4(LX) U35.5(LX)
NetQ4_1: Q4.1(G) R64.1 R65.1 R66.2
NetQ5_1: Q5.1(G) R72.2
NetQ6_1: Q6.1 R73.2
NetQ6_3: Q6.3 R72.1
NetQ7_1: Q7.1(B) R85.2 R385.2
NetQ7_2: Q7.2(E) R84.2 R90.1 U38.11(EN)
NetQ8_2: Q8.2(S) R94.1 R97.1 R99.2
NetQ9_2: Q9.2(S) R103.1 R106.1 R107.2
NetQ10_1: Q10.1(B) R386.2 R387.2
NetR49_2: R49.2 R51.1 R53.2 R55.2
NetR92_1: R92.1 U38.8(BST)
NetR93_2: R93.2 U38.3(PG)
NetR376_2: R376.2 R380.2 U35.2(FB)
NetR381_1: R381.1 R382.1 U35.9(EN/PWM)
NetU77_2: U77.2(-) U78.1(+)

Not connected (* = marked no-connect by the designer): CN2 64 68 70 72 73; CN3 4 6 33 35 39 41 43 45 46 47 48 49 52 54 58 60 64 66; CN4 16 91; FPC2 4* 15* 16*; U35 1(NC) 3(NC) 6(NC) 10(NC); U38 4(NC)* 12(ENLDO)*; USB2 A8(SUB1)* B8(SUB2)*; USB3 17(UTILITY)*

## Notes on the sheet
- MIPI_LCD
- (near AUDIO1) AUDIO
- TF
- IO
- DC-DC
- Labels drawn without touching a wire or pin: +5V, TP_PWR_DET

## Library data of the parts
AUDIO1 = PJ-3420-A-SMT: Manufacturer: XKB Connectivity(中国星坤); Symbol: PJ-3537-X; Add into BOM: yes; Connector Type: 3.5mm耳机座; Current Rating (Max): 500mA; Voltage Rating (Max): 30V; Soldering Temperature(Max): 235℃
C46 C49-C51 C57 C59 C60 C90 C96 C98 C412 = CAP_0402: Symbol: CapAcitance; Convert to PCB: yes
C52-C56 C58 C61-C64 C71-C77 C82 C83 C85 C88 C89 C91-C93 C97 C99 C397 = CAP_0603: Symbol: CapAcitance; Convert to PCB: yes
C86 C87 = CS22UF35V5*5.4: Manufacturer: ST(先科); Add into BOM: yes
C404-C411 = CAP_0805: Symbol: CapAcitance; Convert to PCB: yes
CN1 = W10001-104MSNER1: Add into BOM: yes
CN2-CN4 = DF40HC(3.0)-100DS-0.4V(58): Add into BOM: yes
D4-D15 D17-D24 D27 D28 = TVS: Add into BOM: yes
D16 D25 = ESD5344D: Manufacturer: KUU; Add into BOM: yes; polarity: 单向; Reverse Stand-Off Voltage (Vrwm): 5V; Maximum Clamping Voltage: 15V; Peak Pulse Current (Ipp): 4A; Peak Pulse Power Dissipation (Ppp): 60W; Breakdown Voltage: 9V; Reverse Leakage Current (Ir): 1uA; Number of Lines: 四路; Type: ESD
D26 = SS34_C8678: Manufacturer: MDD(辰达半导体); Add into BOM: yes; Diode Configuration: 独立式; Forward Voltage (Vf@If): 550mV@3A; Reverse Voltage (Vr): 40V; Rectified Current: 3A; Reverse Leakage Current (Ir): 500uA@40V
FPC2 = OK-06F024-04: Convert to PCB: yes
FPC3 usb = AFC01-S06FCA-00: Manufacturer: JS(钜硕电子); Add into BOM: yes; Locking Feature: 翻盖式; Number of Contacts: 6P; Pitch: 0.5mm; FFC, FCB Thickness: 0.3mm
L6 L7 = L_0402: Symbol: SDCL1005C10NJTDFM01; Add into BOM: yes
L8 = L_0603: Symbol: SDFL1608S100KTF; Add into BOM: yes
L9 = SWPA4020S4R7MT: Manufacturer: Sunlord(顺络); Add into BOM: yes; Tolerance: ±20%; Rated Current: 1.34A; Saturation Current (Isat): 2.5A; DC Resistance (DCR): 98mΩ
L10 L12 = L_1206: Manufacturer: FH(风华); Symbol: CMI321609VR27KT; Add into BOM: yes
L11 = SPM5020T-2R2M-LR: Manufacturer: TDK; Add into BOM: yes; Tolerance: ±20%; Rated Current: 4.6A; Saturation Current (Isat): 7A; DC Resistance (DCR): 37mΩ
Q3 = WPM2301-3/TR: Manufacturer: WILLSEMI(韦尔); Add into BOM: yes; Drain Source Voltage (Vdss): 20V; Continuous Drain Current (Id): 2.7A; Drain Source On Resistance (RDS(on)@Vgs,Id): 90mΩ@4.5V,2.2A; Power Dissipation (Pd): 1.4W; Gate Threshold Voltage (Vgs(th)@Id): 400mV@250uA; Total Gate Charge (Qg@Vgs): 4nC@4.5V; Input Capacitance (Ciss@Vds): 300pF@10V; Reverse Transfer Capacitance (Crss@Vds): 60pF@10V
Q4 Q5 = WPM2015-3/TR: Manufacturer: WILLSEMI(韦尔); Add into BOM: yes; Type: 1个P沟道; Drain Source Voltage (Vdss): 20V; Continuous Drain Current (Id): 2.4A; Drain Source On Resistance (RDS(on)@Vgs,Id): 110mΩ@4.5V,2.7A; Power Dissipation (Pd): 1.1W; Gate Threshold Voltage (Vgs(th)@Id): 400mV@250uA; Total Gate Charge (Qg@Vgs): 7.3nC@4.5V; Input Capacitance (Ciss@Vds): 534pF@10V; Reverse Transfer Capacitance (Crss@Vds): 54pF@10V
Q6 = S8050_SOT_NPN: Symbol: NPN; Convert to PCB: yes
Q7 Q10 = S8550_SOT_PNP: Symbol: PNP; Convert to PCB: yes
Q8 Q9 = 2SK3018FPDT106: Manufacturer: ROHM(罗姆); Add into BOM: yes
R49-R57 R59 R376 R377 R380-R382 = Res_0402: Symbol: 电阻; Convert to PCB: yes
R58 R60-R66 R69-R75 R84-R107 R385-R387 = Res_0603: Symbol: 电阻; Convert to PCB: yes
R389 R390 = Res_0805: Symbol: 电阻; Convert to PCB: yes
TP1-TP4 = Test-Point: Add into BOM: yes
U30 = B5819WS: Symbol: B5819WS_C9900015711; Add into BOM: yes
U35 = SY7203DBC: Manufacturer: silergy(矽力杰); Add into BOM: yes; Input Voltage: 2.8V~30V; Switch Frequency: 1MHz; Channels: 1; Output Current: 4A; Dimming: PWM; Topology: 升压
U36 = SY8113BADC: Manufacturer: silergy(矽力杰); Add into BOM: yes; Function: 降压型; Output Type: 固定; Input Voltage: 4.5V~18V; Output Voltage: 1.2V; Output Current: 3A; Switching Frequency: 500kHz; Synchronous Rectification: 是; Number of Outputs: 1; Topology: 降压式; Quiescent Current (Iq): 100uA; Switch tube (built-in/external): 内置
U37 = 4.7uH 3A: Add into BOM: yes
U38 = NB679GD-Z: Manufacturer: MPS(芯源); Add into BOM: yes
U76 = micro sd卡座: Add into BOM: yes
U77 U78 = 21700: Add into BOM: yes; _: 3
U79 = Type-A_USB3.0_3.4mm: Add into BOM: yes
USB2 = KH-TYPE-C-16P: Manufacturer: kinghelm(金航标); Add into BOM: yes; Connector Type: Type-C; Gender: 母; Number of Contacts: 16P; Number of Ports: 1; Current Rating - Power (Max): 3A
USB3 = KH-HDMI-0002: Manufacturer: kinghelm(金航标); Add into BOM: yes; Connector Type: HDMI-C; Gender: 母; Current Rating (Max): 500mA; Rated Voltage (Max): 40V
